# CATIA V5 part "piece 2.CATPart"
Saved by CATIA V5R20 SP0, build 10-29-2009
Part number: piece 2
Bounding box of the stored display mesh (mm): x -20 to 20, y -219.988 to 19.988, z 0 to 10
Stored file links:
  D:\Dropbox\IAO_2011\MMS_GR1\jdubreuilr\jdubreuilr\jdubreuilr\piece 2.CATPart
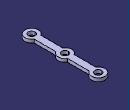
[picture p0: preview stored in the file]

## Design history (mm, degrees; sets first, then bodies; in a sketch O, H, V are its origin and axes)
Set1
  Point1: type OnPlane, Support xy-plane, H 0, V 0, Direction (1, 0, 0)
  Point2: type OnPlane, Support xy-plane, H 0, V -100, Direction (1, 0, 0)
  Point3: type OnPlane, Support xy-plane, H 0, V -200, Direction (1, 0, 0)
  Line1: type Normal, RefPoint Point1, RefSkin end face of Pad1, Start 0, End 20
  Line2: type Normal, RefPoint Point2, RefSkin end face of Pad1, Start 0, End 20
  Line3: type Normal, RefPoint Point3, RefSkin end face of Pad1, Start 0, End 20
Body1 (main body)
  Sketch1 on xy-plane, origin (0, 0, 0), H (1, 0, 0), V (0, 1, 0)
    line L1 (-10, -17.3205) -> (-10, -82.6795)
    point P1 (-10, -17.3205)
    point P2 (-10, -82.6795)
    line L2 (10, -17.3205) -> (10, -82.6795)
    point P3 (10, -17.3205)
    point P4 (10, -82.6795)
    line L3 (10, -117.3205) -> (10, -182.6795)
    point P5 (10, -117.3205)
    point P6 (10, -182.6795)
    line L4 (-10, -117.3205) -> (-10, -182.6795)
    point P7 (-10, -117.3205)
    point P8 (-10, -182.6795)
    arc A1 centre (0, 0) radius 20 from (10, -17.3205) to (-10, -17.3205) ccw
    point P9 (-10, -17.3205)
    point P10 (10, -17.3205)
    arc A2 centre (0, -100) radius 20 from (-10, -82.6795) to (-10, -117.3205) ccw
    point P11 (0, -100)
    point P12 (-10, -117.3205)
    point P13 (-10, -82.6795)
    reference projected point E1 (0, -100) from Point2
    arc A3 centre (0, -100) radius 20 from (10, -117.3205) to (10, -82.6795) ccw
    point P14 (0, -100)
    point P15 (10, -117.3205)
    point P16 (10, -82.6795)
    reference projected point E2 (0, -100) from Point2
    arc A4 centre (0, -200) radius 20 from (-10, -182.6795) to (10, -182.6795) ccw
    point P17 (0, -200)
    point P18 (-10, -182.6795)
    point P19 (10, -182.6795)
    reference projected point E3 (0, -200) from Point3
    circle A5 centre (0, -200) radius 10
    circle A6 centre (0, -100) radius 10
    circle A7 centre (0, 0) radius 10
    distance L1 V = 10
    distance L2 V = 10
    radius A1 = 20
    radius A2 = 20
    radius A3 = 20
    radius A4 = 20
    radius A7 = 10
    radius A6 = 10
    radius A5 = 10
    vertical: L1 V, L2 V, L3 V, L4 V
    coincidence: P5 L2, P7 L1, P9 L1, P10 L2, P1 P9, P10 P3, P11 V, P12 L1, P13 L1, P11 E1, P14 V, P15 L3, P16 L2, P14 E2, P16 P4, P13 P2, P12 P7, P15 P5, P17 V, P18 L4, P19 P6, P8 P18, P17 E3
  Pad1: profile Sketch1, direction (0, 0, 1), length 10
